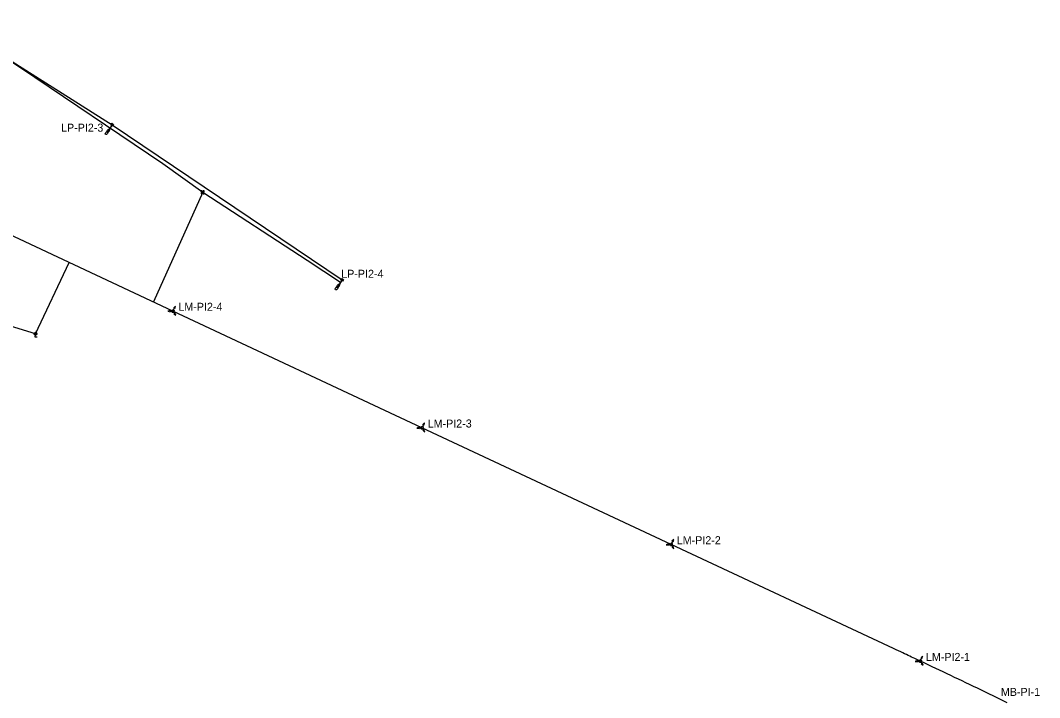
# Model space of a CAD drawing. Extents: x 1689971 to 1704302, y 703122 to 745602.
# Drawn here: x 1699384 to 1700403, y 716988 to 717665 of the extents above; entities that cross this region are included whole.
import ezdxf

# ---------------------------------------------------------------- set-up
doc = ezdxf.new("R2010")
doc.units = 0
for name, color, linetype in [('_CIVIL_CONSTRUCTION', 7, 'Continuous'), ('RD_X_Cells', 7, 'Continuous'), ('RD_X_Concrete_Barrier', 7, 'Continuous'), ('SC_Scratch3', 7, 'Continuous'), ('SC_Scratch4', 7, 'Continuous'), ('SV_X_Control_Cells_Found', 7, 'Continuous'), ('SV_X_Mon_Cells_Found', 7, 'Continuous'), ('SV_X_Random_Point', 7, 'Continuous')]:
    doc.layers.add(name, color=color, linetype=linetype)

msp = doc.modelspace()

# ---------------------------------------------------------------- linework, layer by layer
at = {"layer": '_CIVIL_CONSTRUCTION'}
for p, q in [((1699359.1, 717634.4), (1699384.1, 717618.3)), ((1699384.1, 717618.3), (1699526.6, 717522.1)), ((1699526.6, 717522.1), (1699566.4, 717493.5)), ((1699566.4, 717493.5), (1699517.1, 717383.8)), ((1699566.4, 717493.5), (1699670.7, 717425.4)), ((1699399.2, 717351.7), (1699432.8, 717423.3)), ((1699399.2, 717351.7), (1699251.1, 717397.5))]:
    msp.add_line(p, q, dxfattribs=at)
at = {"layer": 'RD_X_Cells'}
for p, q in [((1699536.6, 717374.6), (1699287.6, 717491.3)), ((1699785.6, 717258), (1699536.6, 717374.6)), ((1700034.7, 717141.3), (1699785.6, 717258)), ((1700256.8, 717037.2), (1700034.7, 717141.3))]:
    msp.add_line(p, q, dxfattribs=at)
for points in [[(1700283.7, 717024.6), (1700282.3, 717025.3), (1700273.3, 717029.5), (1700264.3, 717033.7), (1700256.8, 717037.2)], [(1700370.5, 716983), (1700362.7, 716986.8), (1700340, 716997.9), (1700311, 717011.8), (1700289.8, 717021.7), (1700283.7, 717024.6)]]:
    msp.add_open_spline(points, degree=3, dxfattribs=at)
at = {"layer": 'RD_X_Concrete_Barrier'}
for p, q in [((1699475.9, 717561), (1699705.8, 717405.8)), ((1699536.6, 717374.6), (1699287.6, 717491.3)), ((1699785.6, 717258), (1699536.6, 717374.6)), ((1700034.7, 717141.3), (1699785.6, 717258)), ((1700256.8, 717037.2), (1700034.7, 717141.3))]:
    msp.add_line(p, q, dxfattribs=at)
msp.add_lwpolyline([(1699321.6, 717665.3), (1699342.4, 717646.6), (1699359.1, 717634.4), (1699475.9, 717561)], dxfattribs=at)
for points in [[(1700283.7, 717024.6), (1700282.3, 717025.3), (1700273.3, 717029.5), (1700264.3, 717033.7), (1700256.8, 717037.2)], [(1700370.5, 716983), (1700362.7, 716986.8), (1700340, 716997.9), (1700311, 717011.8), (1700289.8, 717021.7), (1700283.7, 717024.6)]]:
    msp.add_open_spline(points, degree=3, dxfattribs=at)
at = {"layer": 'SC_Scratch3'}
msp.add_lwpolyline([(1699400, 717354.7), (1699398.5, 717348.8), (1699400.8, 717348.8)], dxfattribs=at)
msp.add_circle((1699399.2, 717351.8), 1.3, dxfattribs=at)
at = {"layer": 'SC_Scratch4'}
msp.add_line((1699566.4, 717493.5), (1699566.4, 717493.5), dxfattribs=at)
for points in [[(1699566, 717495), (1699564.9, 717495), (1699564.9, 717493.9)], [(1699564.9, 717493.1), (1699564.9, 717492), (1699566, 717492)], [(1699565.3, 717494.5), (1699565.3, 717492.5), (1699566.4, 717492.5)], [(1699566.3, 717494.5), (1699567.6, 717494.5)], [(1699567.9, 717493.9), (1699567.9, 717495), (1699566.8, 717495)], [(1699566.8, 717492), (1699567.9, 717492), (1699567.9, 717493.1)], [(1699567, 717494.5), (1699567, 717492.5)]]:
    msp.add_lwpolyline(points, dxfattribs=at)
at = {"layer": 'SV_X_Control_Cells_Found'}
for p, q in [((1699475.9, 717561), (1699473.2, 717556.8)), ((1699705.8, 717405.8), (1699703, 717401.6)), ((1699537.3, 717376), (1699538.2, 717377.7)), ((1699539.2, 717379.6), (1699537.5, 717377.8)), ((1699538.6, 717377.2), (1699539.2, 717379.6)), ((1699533.9, 717375.1), (1699531.5, 717374.4)), ((1699531.5, 717374.4), (1699534, 717373.8)), ((1699535.5, 717374.6), (1699533.7, 717374.5)), ((1699537.2, 717373.7), (1699538.2, 717372.2)), ((1699537.5, 717372), (1699539.4, 717370.4)), ((1699539.4, 717370.4), (1699538.6, 717372.7)), ((1699782.9, 717258.5), (1699780.6, 717257.7)), ((1699780.6, 717257.7), (1699783, 717257.2)), ((1699784.6, 717257.9), (1699782.8, 717257.8)), ((1699786.2, 717257), (1699787.2, 717255.5)), ((1699786.4, 717259.4), (1699787.2, 717261)), ((1699788.2, 717262.9), (1699786.5, 717261.1)), ((1699786.6, 717255.4), (1699788.4, 717253.7)), ((1699788.4, 717253.7), (1699787.6, 717256.1)), ((1699787.7, 717260.5), (1699788.2, 717262.9)), ((1700035.4, 717142.7), (1700036.2, 717144.3)), ((1700037.2, 717146.3), (1700035.5, 717144.4)), ((1700036.7, 717143.9), (1700037.2, 717146.3)), ((1700031.9, 717141.8), (1700029.6, 717141)), ((1700029.6, 717141), (1700032, 717140.5)), ((1700033.6, 717141.2), (1700031.8, 717141.1)), ((1700035.3, 717140.4), (1700036.3, 717138.9)), ((1700035.6, 717138.7), (1700037.5, 717137)), ((1700037.5, 717137), (1700036.7, 717139.4)), ((1700281, 717025.1), (1700278.6, 717024.3)), ((1700278.6, 717024.3), (1700281, 717023.8)), ((1700282.6, 717024.5), (1700280.8, 717024.4)), ((1700284.3, 717023.7), (1700285.3, 717022.2)), ((1700284.4, 717026.1), (1700285.2, 717027.7)), ((1700286.1, 717029.6), (1700284.5, 717027.8)), ((1700284.7, 717022), (1700286.5, 717020.4)), ((1700285.7, 717027.2), (1700286.1, 717029.6)), ((1700286.5, 717020.4), (1700285.7, 717022.8))]:
    msp.add_line(p, q, dxfattribs=at)
for points in [[(1699477.3, 717561.2), (1699476.2, 717559.6), (1699474.5, 717560.7), (1699475.7, 717562.4)], [(1699707.2, 717406.1), (1699706.1, 717404.4), (1699704.4, 717405.5), (1699705.5, 717407.2)]]:
    msp.add_lwpolyline(points, close=True, dxfattribs=at)
for centre, start, end in [((1699537.6, 717376.6), 28.3759, 97.4538), ((1699534.9, 717374.5), 148.3759, 217.4538), ((1699537.6, 717373.2), 268.3759, 337.4538), ((1699783.9, 717257.9), 148.3759, 217.4538), ((1699786.7, 717260), 28.3759, 97.4538), ((1699786.6, 717256.5), 268.3759, 337.4538), ((1700035.7, 717143.3), 28.8461, 97.924), ((1700032.9, 717141.2), 148.8461, 217.924), ((1700035.6, 717139.8), 268.8461, 337.924), ((1700281.9, 717024.5), 149.4707, 218.5486), ((1700284.7, 717026.7), 29.4707, 98.5486), ((1700284.7, 717023.2), 269.4707, 338.5486)]:
    msp.add_arc(centre, 1.13, start, end, dxfattribs=at)
for centre, major_axis, ratio in [((1699472, 717555.1), (-1.11, -1.66), 0.5), ((1699701.9, 717400), (-1.11, -1.66), 0.5), ((1699536.6, 717374.6), (0.73, 1.42), 0.625), ((1699785.6, 717258), (0.73, 1.42), 0.625), ((1700034.7, 717141.3), (0.72, 1.43), 0.625), ((1700283.7, 717024.6), (0.7, 1.44), 0.625)]:
    msp.add_ellipse(centre, major_axis=major_axis, ratio=ratio, dxfattribs=at)
at = {"layer": 'SV_X_Mon_Cells_Found'}
for p, q in [((1699475.9, 717561), (1699470.4, 717552.7)), ((1699705.8, 717405.8), (1699700.3, 717397.5))]:
    msp.add_line(p, q, dxfattribs=at)
for points in [[(1699477.3, 717561.2), (1699476.2, 717559.6), (1699474.5, 717560.7), (1699475.7, 717562.4)], [(1699707.2, 717406.1), (1699706.1, 717404.4), (1699704.4, 717405.5), (1699705.5, 717407.2)]]:
    msp.add_lwpolyline(points, close=True, dxfattribs=at)
for centre in [(1699470.4, 717552.7), (1699700.3, 717397.5)]:
    msp.add_ellipse(centre, major_axis=(-1.11, -1.66), ratio=0.5, dxfattribs=at)
at = {"layer": 'SV_X_Random_Point'}
msp.add_line((1699670.7, 717425.4), (1699704.2, 717403.5), dxfattribs=at)

# ---------------------------------------------------------------- texts
for s, p in [('LP-PI2-3', (1699424.8, 717554)), ('LP-PI2-4', (1699704.9, 717407.9)), ('LM-PI2-4', (1699542.1, 717374.9)), ('LM-PI2-3', (1699791.3, 717258.2)), ('LM-PI2-2', (1700040.3, 717141.5)), ('LM-PI2-1', (1700289.4, 717024.8)), ('MB-PI-1', (1700364.3, 716989.8))]:
    msp.add_text(s, height=8, dxfattribs=at).set_placement(p)

doc.saveas('drawing.dxf')
